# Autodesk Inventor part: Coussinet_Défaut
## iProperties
Shininess: 64.0
Length Units: 11269
Angle Units: 11279
Time Units: 11290
Mass Units: 11283
Length Display Precision: 3
Angle Display Precision: 2
Compacted: True
Part Number: Coussinet_Défaut
Document SubType Name: Modeling
Created: 2006-01
Material: Par défaut
Designer: Fricot
Density: 0.0
Volumn: 0.0
Area: 0.0
PropertySet Name: Model Information
Control State: 0
Master: False
Checked Out: False
Author: Fricot
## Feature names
1. Base1
